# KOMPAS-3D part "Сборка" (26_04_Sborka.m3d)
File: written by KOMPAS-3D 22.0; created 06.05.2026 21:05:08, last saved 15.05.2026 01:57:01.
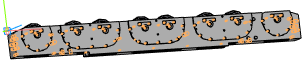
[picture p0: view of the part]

Document properties: Автор: taras; Полное имя файла: E:\test_kompas\all_v20\26_04_Sborka.m3d

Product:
- Component [detail]: Деталь  | qty 1  | pos. 2  | Масса: 261.985445; source file: ..\all_v22\3.1.8 дет.45 Балка(оригинал) (1).m3d
- Component [detail]: Деталь  | qty 1  | pos. 3  | Масса: 21.934157; Организация: TMK; Автор: TMK; source file: ..\all_v22\3.1.8  дет.46.2 Крышка балки (2).m3d
- Component [detail]: Деталь  | qty 1  | pos. 4  | Масса: 21.934157; Организация: TMK; Автор: TMK; source file: ..\all_v22\3.1.8  дет.46.2 Крышка балки (2).m3d
- Component [detail]: Деталь  | qty 1  | pos. 5  | Масса: 9.688835; source file: ..\all_v22\Крышка балки 1 окончательная (3).m3d
- Component [detail]: Деталь  | qty 1  | pos. 6  | Масса: 2.046242; Организация: TMK; Автор: TMK; source file: ..\all_v22\3.1.8 дет.74 Ось кронштейна крепления опорного ролика(новый блок) (1).m3d
- Component [detail]: Деталь  | qty 1  | pos. 7  | Масса: 2.046242; Организация: TMK; Автор: TMK; source file: ..\all_v22\3.1.8 дет.74 Ось кронштейна крепления опорного ролика(новый блок) (1).m3d
- Component [detail]: Деталь  | qty 1  | pos. 8  | Масса: 2.046242; Организация: TMK; Автор: TMK; source file: ..\all_v22\3.1.8 дет.74 Ось кронштейна крепления опорного ролика(новый блок) (1).m3d
- Component [detail]: Деталь  | qty 1  | pos. 12  | Масса: 19.948382; Автор: taras; source file: ..\all_v22\05.04 крышка200.m3d
- Component [detail]: Деталь  | qty 1  | pos. 13  | Масса: 2.046242; Организация: TMK; Автор: TMK; source file: ..\all_v22\3.1.8 дет.74 Ось кронштейна крепления опорного ролика(новый блок) (1).m3d
- Component [detail]: Деталь  | qty 1  | pos. 14  | Масса: 2.046242; Организация: TMK; Автор: TMK; source file: ..\all_v22\3.1.8 дет.74 Ось кронштейна крепления опорного ролика(новый блок) (1).m3d
- Component [detail]: Деталь  | qty 1  | pos. 15  | Масса: 9.688835; source file: ..\all_v22\Крышка балки 1 окончательная (3).m3d
- Component [detail]: Деталь  | qty 1  | pos. 16  | Масса: 2.046242; Организация: TMK; Автор: TMK; source file: ..\all_v22\3.1.8 дет.74 Ось кронштейна крепления опорного ролика(новый блок) (1).m3d
- Component [standard]: Винт М10-6gx20 ГОСТ 11738-84  | qty 31  | pos. 17  | Масса: 0.02351; Раздел спецификации: Стандартные изделия; Рассекать на разрезах: no
- Component [detail]: Деталь  | qty 1  | pos. 19  | Масса: 2.046242; Организация: TMK; Автор: TMK; source file: ..\all_v22\3.1.8 дет.74 Ось кронштейна крепления опорного ролика(новый блок) (1).m3d
- Component [detail]: Деталь  | qty 1  | pos. 20  | Масса: 2.046242; Организация: TMK; Автор: TMK; source file: ..\all_v22\3.1.8 дет.74 Ось кронштейна крепления опорного ролика(новый блок) (1).m3d
- Component [detail]: Деталь  | qty 1  | pos. 21  | Масса: 0.134151; Организация: TMK; Автор: TMK; source file: ..\all_v22\Planka_rigelnaya (1).m3d
- Component [detail]: Деталь  | qty 1  | pos. 22  | Масса: 0.134151; Организация: TMK; Автор: TMK; source file: ..\all_v22\Planka_rigelnaya (1).m3d
- Component [detail]: Деталь  | qty 1  | pos. 23  | Масса: 0.134151; Организация: TMK; Автор: TMK; source file: ..\all_v22\Planka_rigelnaya (1).m3d
- Component [detail]: Деталь  | qty 1  | pos. 24  | Масса: 0.134151; Организация: TMK; Автор: TMK; source file: ..\all_v22\Planka_rigelnaya (1).m3d
- Component [detail]: Деталь  | qty 1  | pos. 25  | Масса: 0.134151; Организация: TMK; Автор: TMK; source file: ..\all_v22\Planka_rigelnaya (1).m3d
- Component [detail]: Деталь  | qty 1  | pos. 26  | Масса: 0.134151; Организация: TMK; Автор: TMK; source file: ..\all_v22\Planka_rigelnaya (1).m3d
- Component [detail]: Деталь  | qty 1  | pos. 27  | Масса: 0.134151; Организация: TMK; Автор: TMK; source file: ..\all_v22\Planka_rigelnaya (1).m3d
- Component [detail]: Деталь  | qty 1  | pos. 28  | Масса: 0.134151; Организация: TMK; Автор: TMK; source file: ..\all_v22\Planka_rigelnaya (1).m3d
- Component [standard]: Подшипник 318 ГОСТ 8338-75  | qty 7  | pos. 29  | Масса: 4.954; Раздел спецификации: Стандартные изделия; additional columns: 318
- Component [standard]: Болт М16-6gx170 ГОСТ 7795-70  | qty 6  | pos. 30  | Масса: 0.2633; Раздел спецификации: Стандартные изделия; Рассекать на разрезах: no
- Component [standard]: Винт М12-6gx20 ГОСТ 11738-84  | qty 16  | pos. 31  | Масса: 0.03416; Раздел спецификации: Стандартные изделия; Рассекать на разрезах: no
- Part/product: Сборка
    Масса: 400.156123

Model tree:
1. Отверстие:2  (with: Вырезать элемент выдавливания:22, Элемент выдавливания:2, Вырезать элемент выдавливания:16, Элемент выдавливания:5, Фаска:1, Элемент выдавливания:3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)  (labels: Скругление:2; Скругление:1; Скругление:2; Скругление:2)
     Ориентация = 2

Referenced files in C:\Program Files\ASCON\KOMPAS-3D v22\Libs\PolynomLib\DATA\vault\Methods\Kompas\3D\: PLib_Screw_GOST_11738_1500.m3d, PLib_Bolt_1_900.m3d
Referenced files in C:\Program Files\ASCON\KOMPAS-3D v22\Libs\PolynomLib\DATA\vault\Methods\Kompas\3D\Bearings\8338_75\: PLib_Bearing_GOST_8338_75_712.a3d
Referenced files in E:\test_kompas\all_v22\: 3.1.8 дет.45 Балка(оригинал) (1).m3d, 3.1.8  дет.46.2 Крышка балки (2).m3d, Крышка балки 1 окончательная (3).m3d, 3.1.8 дет.74 Ось кронштейна крепления опорного ролика(новый блок) (1).m3d, 05.04 крышка200.m3d, Planka_rigelnaya (1).m3d
Referenced files in C:\Program Files\ASCON\KOMPAS-3D v23 Study\Libs\PolynomLib\DATA\vault\Methods\Kompas\3D\: PLib_Screw_GOST_11738_1500.m3d, PLib_Bolt_1_900.m3d
Referenced files in C:\Program Files\ASCON\KOMPAS-3D v23 Study\Libs\PolynomLib\DATA\vault\Methods\Kompas\3D\Bearings\8338_75\: PLib_Bearing_GOST_8338_75_712.a3d
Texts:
  BOSimple***PART:419c87c2-70e2-98da-c2de-5eacb226740c***SHORTLOC:Root±30±20±10±80±10±GMC90[Нет;Без покрытия;Без указания материала;1,5;-;20;10]
  BOSimple***PART:61ab3e34-d848-86f0-c4aa-2b99c9f755c6***SHORTLOC:Root±Pac-16±Pac10±GMC20±GMC30±GMC10±GMC24[90;190;43]
  BOSimple***PART:9b7fe62b-1d30-3d6e-6be6-01a0e1891a36***SHORTLOC:Root±30±20±10±80±10±©{}30±©{BASE}130±190[Нет;Без покрытия;Без указания материала;170;16;22;2;-]
  BOSimple***PART:d3aa4c40-18a1-862e-ff95-3d42db175957***SHORTLOC:Root±30±20±10±80±10±GMC90[Нет;Без покрытия;Без указания материала;1,75;-;20;12]
  hole1
  hole2
  Радус под головкой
